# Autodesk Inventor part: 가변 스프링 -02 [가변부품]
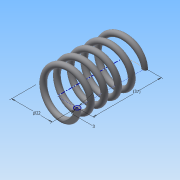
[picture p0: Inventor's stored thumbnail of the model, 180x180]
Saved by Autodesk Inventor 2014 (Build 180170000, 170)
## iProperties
Created: 2015-09
Part Number: 가변 스프링 -02 [가변부품]
Material: 강철, 탄소
Document SubType Name: Modeling
Designer: study
Density: 7.87 g/cm^3
Appearance: 반연마
Mass: 18.9134 g
Surface Area: 32.569 cm^2
Volume: 2.40323 cm^3
Author: study
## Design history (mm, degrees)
sketch "스케치1"
  geometry: L1 (0, 0)-(11, 0); L2 (11, 0)-(11, 28.893); L3 (11, 28.893)-(0, 28.893); L4 (0, 28.893)-(0, 0); C1 r 1.5 at (11, 0)
  constraints: 8 end point, 2 parallel, 1 centre point, 1 coincident, 1 horizontal, 1 perpendicular
  dimensions: "d0" = 3 diameter of C1; "d1" = 22 diameter of L2 L4; "d2" = 28.89259 distance of L1.end L2.end (derived)
feature "코일1" pitch "d3" = 10; turns "d5" = 5; dims "d4" = 28.89259 (= d2), "d6" = 0, angle "d7" = 90 deg, angle "d8" = 90 deg, "d9" = 0, "d10" = 0
node "작업 평면1"
sketch "스케치2"
  geometry: L1 (-12.5, 0)-(-9.5, 0) reference; L2 (-12.5, 0)-(-9.5, 0) reference; 1 further point
  constraints: 2 horizontal alignment
extrude "돌출1" cut sketch "스케치2" stored distance "d12" = 10; taper "d13" = 0 deg
node "작업 평면2"
sketch "스케치3"
  geometry: L1 (-9.5, 0)-(-12.5, 0) reference; 1 further point
  constraints: 1 horizontal alignment
extrude "돌출2" cut sketch "스케치3" stored distance "d15" = 10; taper "d16" = 0 deg
node "솔리드1"
node "절단 모서리 투영1"
node "절단 모서리 투영2"
node "절단 모서리 투영3"
other parameters: "d11" = 0, "d14" = 28.89259 (= d2)
